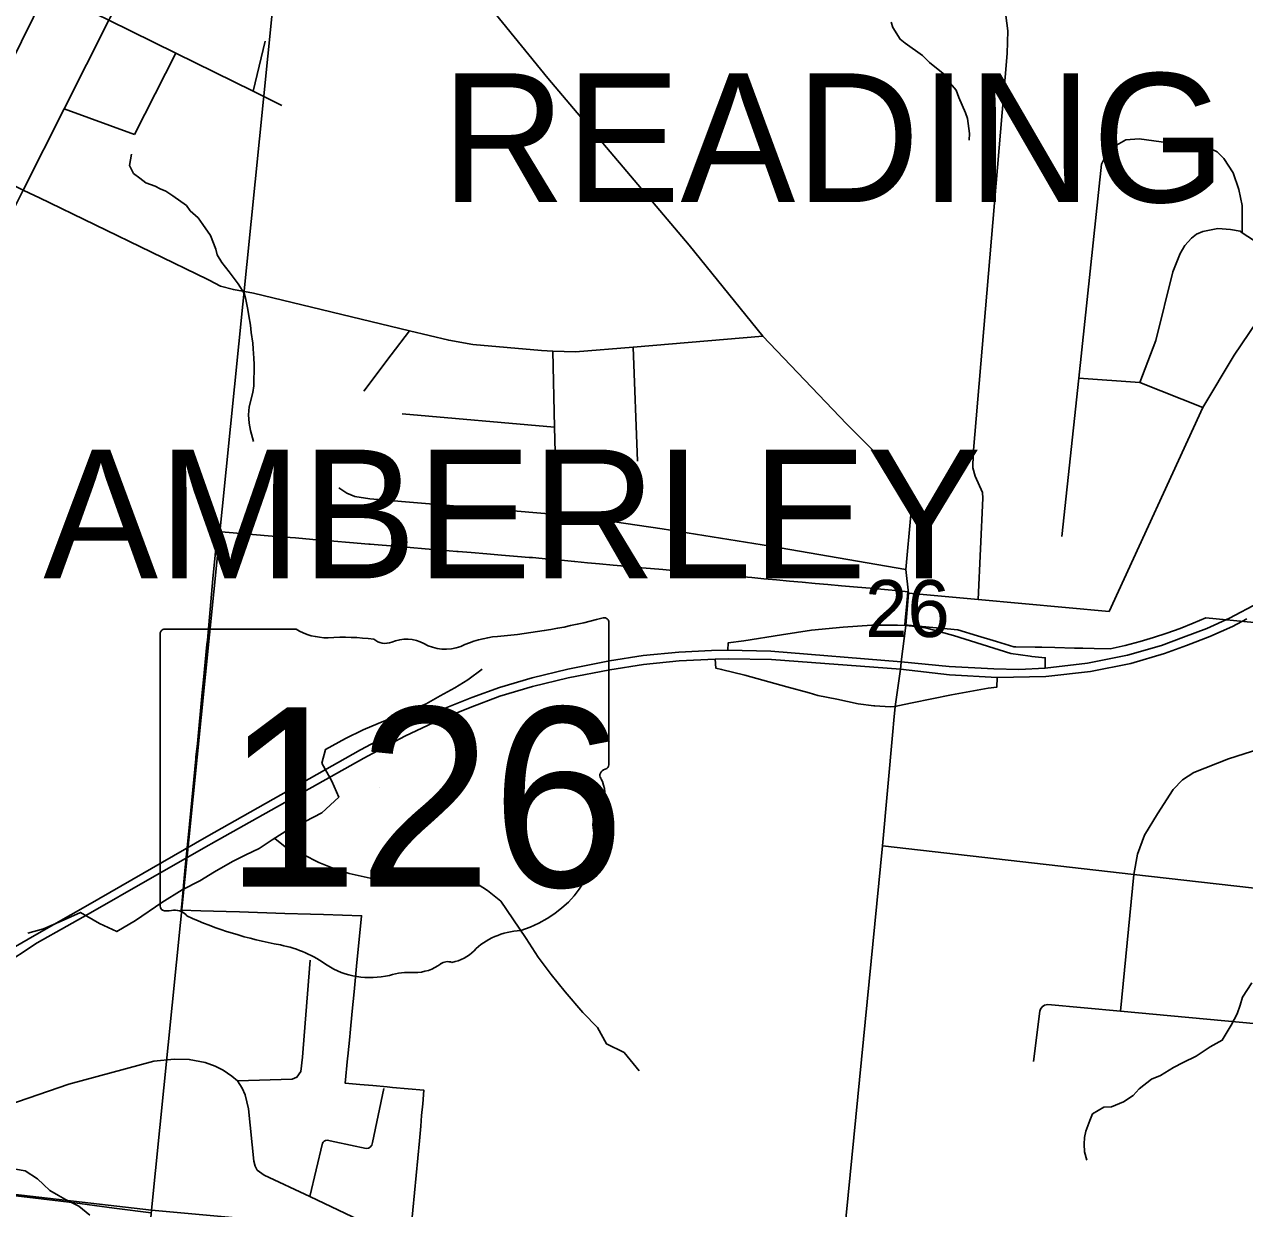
# Model space of a CAD drawing. Extents: x 0 to 34, y -3.9 to 26.2.
# Drawn here: x 3.881 to 4.778, y 18.269 to 19.139 of the extents above; entities that cross this region are included whole.
import ezdxf

# ---------------------------------------------------------------- set-up
doc = ezdxf.new("R2010")
doc.units = 0
for name, color, linetype in [('GM_X_City_Street', 7, 'Continuous'), ('GM_X_Corporation', 7, 'Continuous'), ('GM_X_Corporation_Text', 7, 'Continuous'), ('GM_X_County_Road', 7, 'Continuous'), ('GM_X_Interchange_Ramps', 7, 'Continuous'), ('GM_X_Minor_River', 7, 'Continuous'), ('GM_X_Section', 7, 'Continuous'), ('GM_X_Section_Text', 7, 'Continuous'), ('GM_X_State_Location', 7, 'Continuous'), ('GM_X_State_Route', 7, 'Continuous'), ('GM_X_State_Shield', 7, 'Continuous')]:
    doc.layers.add(name, color=color, linetype=linetype)

msp = doc.modelspace()

# ---------------------------------------------------------------- linework, layer by layer
at = {"layer": 'GM_X_City_Street'}
for p, q in [((4.04921, 19.08997), (4.05792, 19.12696)), ((3.9621, 19.05813), (3.99227, 19.11804)), ((3.91032, 19.07708), (3.9621, 19.05813)), ((4.3318, 18.81818), (4.32849, 18.90197)), ((4.27081, 18.84297), (4.15861, 18.85279))]:
    msp.add_line(p, q, dxfattribs=at)
for points in [[(4.67826, 18.70753), (4.74714, 18.8575), (4.77032, 18.89605), (4.81434, 18.96112), (4.90964, 19.07416), (4.93258, 19.10091), (4.93801, 19.1057), (4.94914, 19.11072), (5.07747, 19.16082), (5.09517, 19.17059), (5.09789, 19.1728), (5.1003, 19.17805), (5.11213, 19.29962), (5.11226, 19.30455), (5.1098, 19.31221), (5.09188, 19.36259)], [(4.5821, 18.7164), (4.58558, 18.79088), (4.58531, 18.79507), (4.57992, 18.80698), (4.57819, 18.81311), (4.57845, 18.82335), (4.60185, 19.10028), (4.60344, 19.1177), (4.60387, 19.13439), (4.60021, 19.16284), (4.59975, 19.1664), (4.5978, 19.17898), (4.59474, 19.19273), (4.58084, 19.22727), (4.57709, 19.24409), (4.5739, 19.26733), (4.57328, 19.28266), (4.57447, 19.28971), (4.58587, 19.35078)], [(3.42211, 19.34248), (3.42358, 19.34321), (3.42718, 19.34343), (3.49478, 19.33455), (3.5723, 19.32436), (3.65582, 19.28345), (3.73336, 19.24545), (3.80179, 19.21193), (3.89772, 19.16464), (3.94313, 19.14226), (3.99227, 19.11804), (4.04921, 19.08997), (4.07036, 19.07954)], [(3.83878, 18.93501), (3.88028, 19.01742), (3.91032, 19.07708), (3.94313, 19.14226), (3.94384, 19.14366), (3.96986, 19.19533), (4.00778, 19.27066)], [(3.83562, 19.03913), (3.89645, 19.16207), (3.89772, 19.16464)], [(4.64365, 18.76275), (4.65597, 18.87903), (4.67266, 19.03649), (4.67624, 19.04323), (4.6821, 19.04952), (4.69056, 19.05423), (4.70044, 19.05511), (4.7526, 19.04801), (4.75784, 19.0456), (4.76264, 19.04054), (4.76958, 19.0301), (4.77367, 19.01778), (4.77617, 19.006), (4.77613, 18.98603)], [(4.70078, 18.87589), (4.71256, 18.9067), (4.72524, 18.95724), (4.73051, 18.97077), (4.73404, 18.97653), (4.73876, 18.98194), (4.74249, 18.98486), (4.74724, 18.98703), (4.75829, 18.98902), (4.76758, 18.98834), (4.77455, 18.98706), (4.77613, 18.98603), (4.81434, 18.96112)], [(4.13059, 18.86949), (4.15063, 18.89615), (4.164, 18.91392)], [(4.27241, 18.7788), (4.27081, 18.84297), (4.26941, 18.89907)], [(4.65597, 18.87903), (4.70078, 18.87589), (4.74714, 18.8575)], [(4.11209, 18.7986), (4.11805, 18.79464), (4.12406, 18.79221), (4.13501, 18.79039), (4.27241, 18.7788), (4.28639, 18.77762), (4.34986, 18.76833), (4.42956, 18.75557), (4.52885, 18.73856)], [(4.53098, 18.72113), (4.5821, 18.7164), (4.67826, 18.70753)], [(4.68658, 18.41371), (4.69643, 18.51433), (4.69911, 18.52928), (4.70439, 18.54318), (4.7139, 18.55888), (4.72536, 18.57679), (4.73227, 18.58394), (4.74047, 18.5893), (4.76613, 18.59924), (4.78907, 18.6066), (4.7975, 18.60851), (4.79959, 18.60881), (4.80508, 18.60959), (4.89708, 18.60369), (4.98906, 18.5978), (5.03945, 18.59458), (5.04519, 18.59632), (5.05285, 18.59953), (5.12291, 18.64965)], [(4.51173, 18.53533), (4.69643, 18.51433), (4.943, 18.4863), (4.9457, 18.48511), (4.94732, 18.4837), (4.94851, 18.48197), (4.94965, 18.47928)], [(4.03765, 18.36248), (4.07793, 18.3638), (4.08138, 18.36528), (4.08417, 18.36939), (4.08549, 18.38007), (4.08598, 18.38621), (4.09106, 18.45138)], [(4.62277, 18.37679), (4.62751, 18.41388), (4.62794, 18.41536), (4.62911, 18.41687), (4.63091, 18.41815), (4.63332, 18.41865), (4.68658, 18.41371), (4.92726, 18.39138)], [(4.09075, 18.27748), (4.10013, 18.31674), (4.10069, 18.31748), (4.10148, 18.31828), (4.10244, 18.31876), (4.1036, 18.31892), (4.10925, 18.31763), (4.13227, 18.31284), (4.13403, 18.31317), (4.13533, 18.3139), (4.13635, 18.31516), (4.13693, 18.31727), (4.14515, 18.35692)]]:
    msp.add_lwpolyline(points, dxfattribs=at)
at = {"layer": 'GM_X_Corporation'}
for points in [[(4.16531, 18.25485), (4.17139, 18.31836), (4.17236, 18.3292), (4.17305, 18.33696), (4.17383, 18.34573), (4.17472, 18.35568), (4.15166, 18.35776), (4.14762, 18.35812), (4.13712, 18.35907), (4.12751, 18.35993), (4.11679, 18.3609), (4.11857, 18.37889), (4.11876, 18.38077), (4.12015, 18.39491), (4.12043, 18.39774), (4.12202, 18.41376), (4.12341, 18.42789), (4.12527, 18.44674), (4.12895, 18.48396), (4.1009, 18.48481), (4.09141, 18.4851), (4.07244, 18.48568), (4.0392, 18.48669), (4.02948, 18.48698), (4.02002, 18.48727), (4.0107, 18.48755), (3.99627, 18.48809), (3.9965, 18.49041), (3.99668, 18.49231), (3.99933, 18.51954), (4.00168, 18.54372), (4.00413, 18.56886), (4.0071, 18.59934), (4.0072, 18.60043), (4.0082, 18.61064), (4.01184, 18.64809), (4.01275, 18.65741), (4.01526, 18.68325), (4.01556, 18.68649), (4.01966, 18.7317), (4.02295, 18.76631), (4.06876, 18.76256), (4.08039, 18.76161), (4.09829, 18.76013), (4.10858, 18.75928), (4.11992, 18.75835), (4.1343, 18.75716), (4.13519, 18.75709), (4.144, 18.75635), (4.15346, 18.75556), (4.16464, 18.75463), (4.17558, 18.75371), (4.18759, 18.75271), (4.19892, 18.75176), (4.19997, 18.75168), (4.20947, 18.75089), (4.22088, 18.74995), (4.23186, 18.74905), (4.24356, 18.74809), (4.25204, 18.74739), (4.25444, 18.74717), (4.26624, 18.7461), (4.27569, 18.74525), (4.2855, 18.74436), (4.28572, 18.74434), (4.29489, 18.74347), (4.30377, 18.74262), (4.31369, 18.74167), (4.32238, 18.74084), (4.33137, 18.73998), (4.33486, 18.73965), (4.34121, 18.73911), (4.35027, 18.73834), (4.36016, 18.73751), (4.36875, 18.73678), (4.37364, 18.73637), (4.37819, 18.73595), (4.38772, 18.73507), (4.39667, 18.73425), (4.40615, 18.73338), (4.41562, 18.73251), (4.42452, 18.73169), (4.42777, 18.73139), (4.43382, 18.73085), (4.44343, 18.72998), (4.45281, 18.72913), (4.46233, 18.72827), (4.47156, 18.72744), (4.48169, 18.72652), (4.49329, 18.72548), (4.50275, 18.72462), (4.51313, 18.72368), (4.52422, 18.72268), (4.53037, 18.72212), (4.5294, 18.7107), (4.5285, 18.7011), (4.52819, 18.69783), (4.53319, 18.69735), (4.56725, 18.69408), (4.58158, 18.68976), (4.59565, 18.68553), (4.60835, 18.68171), (4.60977, 18.68168), (4.62389, 18.68139), (4.62884, 18.68129), (4.63832, 18.68107), (4.65297, 18.68073), (4.65898, 18.68059), (4.66739, 18.68039), (4.67906, 18.68012), (4.69012, 18.68264), (4.7011, 18.68552), (4.71097, 18.68844), (4.72075, 18.69164), (4.73044, 18.69514), (4.74002, 18.69891), (4.74949, 18.70296), (4.78505, 18.69949)], [(4.78505, 18.69949), (4.74949, 18.70296), (4.74002, 18.69891), (4.73044, 18.69514), (4.72075, 18.69164), (4.71097, 18.68844), (4.7011, 18.68552), (4.69012, 18.68264), (4.67906, 18.68012), (4.66739, 18.68039), (4.65898, 18.68059), (4.65297, 18.68073), (4.63832, 18.68107), (4.62884, 18.68129), (4.62389, 18.68139), (4.60977, 18.68168), (4.60835, 18.68171), (4.59565, 18.68553), (4.58158, 18.68976), (4.56725, 18.69408), (4.53319, 18.69735), (4.52819, 18.69783), (4.5285, 18.7011), (4.5294, 18.7107), (4.53037, 18.72212), (4.52422, 18.72268), (4.51313, 18.72368), (4.50275, 18.72462), (4.49329, 18.72548), (4.48169, 18.72652), (4.47156, 18.72744), (4.46233, 18.72827), (4.45281, 18.72913), (4.44343, 18.72998), (4.43382, 18.73085), (4.42777, 18.73139), (4.42452, 18.73169), (4.41562, 18.73251), (4.40615, 18.73338), (4.39667, 18.73425), (4.38772, 18.73507), (4.37819, 18.73595), (4.37364, 18.73637), (4.36875, 18.73678), (4.36016, 18.73751), (4.35027, 18.73834), (4.34121, 18.73911), (4.33486, 18.73965), (4.33137, 18.73998), (4.32238, 18.74084), (4.31369, 18.74167), (4.30377, 18.74262), (4.29489, 18.74347), (4.28572, 18.74434), (4.2855, 18.74436), (4.27569, 18.74525), (4.26624, 18.7461), (4.25444, 18.74717), (4.25204, 18.74739), (4.24356, 18.74809), (4.23186, 18.74905), (4.22088, 18.74995), (4.20947, 18.75089), (4.19997, 18.75168), (4.19892, 18.75176), (4.18759, 18.75271), (4.17558, 18.75371), (4.16464, 18.75463), (4.15346, 18.75556), (4.144, 18.75635), (4.13519, 18.75709), (4.1343, 18.75716), (4.11992, 18.75835), (4.10858, 18.75928), (4.09829, 18.76013), (4.08039, 18.76161), (4.06876, 18.76256), (4.02295, 18.76631), (4.01966, 18.7317), (4.01556, 18.68649), (4.01526, 18.68325), (4.01275, 18.65741), (4.01184, 18.64809), (4.0082, 18.61064), (4.0072, 18.60043), (4.0071, 18.59934), (4.00413, 18.56886), (4.00168, 18.54372), (3.99933, 18.51954), (3.99668, 18.49231), (3.9965, 18.49041), (3.99627, 18.48809), (4.0107, 18.48755), (4.02002, 18.48727), (4.02948, 18.48698), (4.0392, 18.48669), (4.07244, 18.48568), (4.09141, 18.4851), (4.1009, 18.48481), (4.12895, 18.48396), (4.12527, 18.44674), (4.12341, 18.42789), (4.12202, 18.41376), (4.12043, 18.39774), (4.12015, 18.39491), (4.11876, 18.38077), (4.11857, 18.37889), (4.11679, 18.3609), (4.12751, 18.35993), (4.13712, 18.35907), (4.14762, 18.35812), (4.15166, 18.35776), (4.17472, 18.35568), (4.17383, 18.34573), (4.17305, 18.33696), (4.17236, 18.3292), (4.17139, 18.31836), (4.16531, 18.25485)], [(3.81079, 18.24369), (3.81469, 18.28506), (3.82386, 18.28399), (3.85122, 18.28078), (3.8618, 18.27954), (3.88323, 18.27703), (3.91823, 18.27293), (3.94703, 18.26903), (3.97417, 18.26561)], [(3.97417, 18.26561), (3.94703, 18.26903), (3.91823, 18.27293), (3.88323, 18.27703), (3.8618, 18.27954), (3.85122, 18.28078), (3.82386, 18.28399), (3.81469, 18.28506), (3.81079, 18.24369)]]:
    msp.add_lwpolyline(points, dxfattribs=at)
at = {"layer": 'GM_X_County_Road'}
msp.add_line((4.52883, 18.6972), (4.53098, 18.72113), dxfattribs=at)
for points in [[(4.53098, 18.72113), (4.52885, 18.73856), (4.53258, 18.77854), (4.53234, 18.78419), (4.5313, 18.7911), (4.52889, 18.79799), (4.52511, 18.80491), (4.52344, 18.80707), (4.48528, 18.84561), (4.42374, 18.91006), (4.36973, 18.97676), (4.2658, 19.09969), (4.16901, 19.21867), (4.16657, 19.22277), (4.16239, 19.22983), (4.15559, 19.25162), (4.13078, 19.3038), (4.12786, 19.30994), (4.12527, 19.3129), (4.12087, 19.31675), (4.11023, 19.32165), (4.0164, 19.36489), (3.97125, 19.38569), (3.90768, 19.42367)], [(3.36715, 19.19868), (3.39229, 19.19223), (3.42359, 19.18468), (3.4673, 19.17661), (3.54493, 19.16227), (3.66913, 19.11339), (3.68493, 19.10718), (3.74097, 19.08512), (3.83562, 19.03913), (3.88028, 19.01742), (3.88909, 19.01315)], [(3.88909, 19.01315), (3.89173, 19.01186), (4.01588, 18.95152), (4.01682, 18.95104)], [(4.01682, 18.95104), (4.02524, 18.94672), (4.03465, 18.94419), (4.04938, 18.94152), (4.164, 18.91392), (4.19299, 18.90693), (4.21074, 18.9038), (4.26106, 18.89942), (4.26941, 18.89907), (4.28607, 18.89837), (4.32849, 18.90197), (4.42374, 18.91006)], [(4.52525, 18.66733), (4.5255, 18.67057), (4.52883, 18.6972)], [(4.51943, 18.6193), (4.5202, 18.6277), (4.52114, 18.63773), (4.52508, 18.66516), (4.52525, 18.66733)], [(4.22817, 17.22723), (4.24049, 17.50456), (4.243, 17.51666), (4.25054, 17.5336), (4.31287, 17.6317), (4.33274, 17.66299), (4.39508, 17.74681), (4.43243, 17.79354), (4.43716, 17.80294), (4.4401, 17.8177), (4.45785, 18.01565), (4.46135, 18.0547), (4.48088, 18.22126), (4.51173, 18.53533), (4.51943, 18.6193)], [(3.76523, 18.29845), (3.77257, 18.30043), (3.85927, 18.3416), (3.88385, 18.34978), (3.91385, 18.36018), (3.97632, 18.37695), (3.99112, 18.37843), (4.0023, 18.37826), (4.01397, 18.37613), (4.02121, 18.37333), (4.02729, 18.37037), (4.03353, 18.36594), (4.03765, 18.36248), (4.0411, 18.35706), (4.0434, 18.35229), (4.04583, 18.34194), (4.04965, 18.3035), (4.05067, 18.29972), (4.05218, 18.29699), (4.05721, 18.29327), (4.09075, 18.27748), (4.1427, 18.25266)]]:
    msp.add_lwpolyline(points, dxfattribs=at)
at = {"layer": 'GM_X_Interchange_Ramps'}
for points in [[(4.52883, 18.6972), (4.52277, 18.6975), (4.50387, 18.69756), (4.48292, 18.69603), (4.45958, 18.69396), (4.43741, 18.69049), (4.40988, 18.68595), (4.39833, 18.68452), (4.39817, 18.67907)], [(4.6214, 18.67457), (4.62029, 18.67467), (4.60605, 18.6768), (4.56405, 18.68996), (4.54428, 18.69531), (4.53877, 18.69621), (4.53129, 18.69697), (4.52883, 18.6972)], [(4.38889, 18.67247), (4.38932, 18.66583), (4.39344, 18.66498), (4.41053, 18.66086), (4.44152, 18.65231), (4.45777, 18.64773)], [(4.63139, 18.66603), (4.63139, 18.67358), (4.6214, 18.67457)], [(4.52114, 18.63773), (4.52314, 18.63828), (4.53363, 18.64046), (4.56256, 18.64635), (4.58931, 18.65111), (4.59581, 18.65199), (4.59592, 18.65905)], [(4.45777, 18.64773), (4.46427, 18.64589), (4.47822, 18.64303), (4.49394, 18.63973), (4.50536, 18.6383), (4.50621, 18.63823), (4.51745, 18.63754), (4.52114, 18.63773)]]:
    msp.add_lwpolyline(points, dxfattribs=at)
at = {"layer": 'GM_X_Minor_River'}
for points in [[(4.5181, 19.14074), (4.51947, 19.13689), (4.52483, 19.1283), (4.52852, 19.12549), (4.54108, 19.11622), (4.54619, 19.11107), (4.55872, 19.10104), (4.56156, 19.09599), (4.56591, 19.09086), (4.56798, 19.08545), (4.57286, 19.07423), (4.57421, 19.06999), (4.57568, 19.05891), (4.57548, 19.05397)], [(4.04955, 18.8325), (4.04721, 18.84058), (4.04628, 18.84594), (4.04576, 18.85204), (4.04638, 18.8581), (4.04908, 18.86863), (4.04965, 18.87355), (4.04988, 18.88913), (4.04968, 18.8937), (4.04919, 18.90056), (4.04898, 18.90475), (4.04778, 18.91278), (4.04723, 18.91812), (4.04598, 18.92502), (4.0454, 18.9296), (4.04379, 18.93689), (4.04281, 18.94112), (4.03817, 18.94853), (4.03166, 18.95716), (4.02624, 18.96423), (4.02266, 18.9697), (4.02168, 18.97392), (4.0179, 18.98396), (4.01215, 18.99218), (4.00891, 18.99688), (4.00303, 19.00206), (4.00015, 19.00598), (3.99017, 19.01324), (3.98498, 19.0165), (3.98087, 19.01818), (3.97715, 19.02024), (3.97041, 19.0228), (3.96598, 19.02603), (3.96118, 19.02964), (3.95837, 19.03546), (3.95984, 19.04377)], [(4.21741, 18.66521), (4.20702, 18.65742), (4.19743, 18.65152), (4.18669, 18.64564), (4.17634, 18.63975), (4.16486, 18.63503), (4.15072, 18.62921), (4.14116, 18.62521), (4.13006, 18.62048), (4.11705, 18.61426), (4.10248, 18.60618), (4.09963, 18.59597), (4.10697, 18.5829), (4.11206, 18.57102), (4.09971, 18.55947), (4.08745, 18.55324), (4.07596, 18.54775), (4.06329, 18.53963), (4.05368, 18.53335), (4.04373, 18.5286), (4.03415, 18.52384), (4.02073, 18.51611), (4.00998, 18.50947), (3.99696, 18.50287), (3.98199, 18.49365), (3.96276, 18.48033), (3.94895, 18.47223), (3.93616, 18.47817), (3.92228, 18.48642), (3.90812, 18.47984), (3.89511, 18.47439), (3.88367, 18.47118)], [(4.06505, 18.54076), (4.07268, 18.53451), (4.08585, 18.52894), (4.0975, 18.52302), (4.10843, 18.51863), (4.11974, 18.51499), (4.13523, 18.51166), (4.14927, 18.51177), (4.16068, 18.51307), (4.17362, 18.51511), (4.18612, 18.51411), (4.199, 18.51273), (4.21182, 18.50868), (4.22157, 18.50242), (4.23129, 18.49463), (4.24015, 18.48153), (4.24975, 18.46729), (4.25859, 18.45343), (4.26822, 18.44071), (4.27861, 18.42796), (4.2916, 18.41289), (4.3024, 18.40166), (4.309, 18.38975), (4.32178, 18.38342), (4.33291, 18.36991)], [(4.66184, 18.30421), (4.66018, 18.31036), (4.66002, 18.31607), (4.66022, 18.321), (4.66115, 18.32552), (4.66412, 18.33338), (4.66622, 18.33823), (4.67439, 18.34322), (4.6801, 18.34336), (4.68899, 18.34717), (4.69601, 18.35182), (4.70038, 18.35658), (4.7094, 18.36381), (4.71597, 18.36657), (4.7257, 18.37225), (4.73269, 18.37614), (4.74237, 18.38068), (4.75252, 18.38748), (4.76145, 18.39243), (4.76797, 18.40357), (4.77247, 18.41174), (4.77463, 18.41812), (4.77638, 18.42412), (4.78325, 18.43448)], [(3.8325, 18.28122), (3.83749, 18.28253), (3.84294, 18.28573), (3.84843, 18.29006), (3.85506, 18.29435), (3.86049, 18.29716), (3.86887, 18.29757), (3.87458, 18.29772), (3.88174, 18.29628), (3.89063, 18.29059), (3.89502, 18.28623), (3.89979, 18.28185), (3.90611, 18.27817), (3.91131, 18.27529), (3.921, 18.27033), (3.92911, 18.26391)]]:
    msp.add_lwpolyline(points, dxfattribs=at)
at = {"layer": 'GM_X_Section'}
for points in [[(3.06078, 19.39362), (4.07507, 19.26688), (3.97441, 18.26756), (2.95688, 18.38489)], [(4.07507, 19.26688), (5.08525, 19.17848), (4.98981, 18.17527), (3.97441, 18.26756)], [(2.95688, 18.38489), (3.97441, 18.26756), (3.88035, 17.25787), (2.86031, 17.36388)]]:
    msp.add_lwpolyline(points, close=True, dxfattribs=at)
at = {"layer": 'GM_X_State_Route'}
msp.add_line((3.97315, 18.511), (4.0167, 18.53588), dxfattribs=at)
for points in [[(4.63139, 18.66603), (4.66233, 18.66953), (4.69194, 18.67546), (4.71672, 18.68269), (4.73295, 18.68861), (4.75006, 18.69519), (4.76673, 18.70265), (4.788, 18.71406)], [(4.0167, 18.53588), (4.01844, 18.53688), (4.13052, 18.59983), (4.16057, 18.61584), (4.18623, 18.6279), (4.20882, 18.63689), (4.23053, 18.64523), (4.25444, 18.65246), (4.28076, 18.65882), (4.31125, 18.66475), (4.33603, 18.66869), (4.36235, 18.67133), (4.38889, 18.67247), (4.39854, 18.67286), (4.43012, 18.6722), (4.52508, 18.66516), (4.56106, 18.66102), (4.59592, 18.65905), (4.63169, 18.6597), (4.66458, 18.66343), (4.69419, 18.66935), (4.71898, 18.67659), (4.73521, 18.68251), (4.75232, 18.68909), (4.76898, 18.69655), (4.77962, 18.70225)], [(3.87275, 18.46022), (3.89033, 18.47045), (3.92765, 18.49157), (4.01504, 18.54187), (4.12803, 18.60584), (4.15572, 18.62064), (4.18304, 18.63354), (4.20998, 18.64439), (4.23032, 18.65168), (4.25423, 18.65892), (4.28055, 18.66528), (4.31104, 18.6712), (4.33582, 18.67515), (4.36214, 18.67778), (4.38618, 18.67881), (4.39817, 18.67907), (4.42975, 18.67842), (4.5255, 18.67057), (4.56069, 18.66723), (4.59358, 18.66537), (4.61193, 18.66496), (4.63139, 18.66603)], [(3.91224, 18.47628), (3.92786, 18.48512), (3.97315, 18.511)], [(3.36566, 18.28122), (3.42099, 18.275), (3.45542, 18.27324), (3.48898, 18.27412), (3.51442, 18.27632), (3.54338, 18.28092), (3.57101, 18.28728), (3.59294, 18.2932), (3.63117, 18.30581), (3.65523, 18.31316), (3.67739, 18.32084), (3.70063, 18.33005), (3.72827, 18.34365), (3.73752, 18.34979), (3.74671, 18.35585), (3.75547, 18.36163), (3.79799, 18.39515), (3.82302, 18.41603), (3.84693, 18.43467), (3.86382, 18.4463), (3.89054, 18.464), (3.91224, 18.47628)]]:
    msp.add_lwpolyline(points, dxfattribs=at)
at = {"layer": 'GM_X_State_Shield'}
for p, q in [((4.31054, 18.59491), (4.31054, 18.6996)), ((3.98096, 18.6912), (3.98096, 18.49108)), ((4.08072, 18.69464), (3.9842, 18.69464)), ((4.31051, 18.59494), (4.31054, 18.59491))]:
    msp.add_line(p, q, dxfattribs=at)
for centre, major_axis, start_param, end_param in [((4.19314, 18.96747), (0.34952, 0), 4.814394, 5.042369), ((4.30689, 18.70003), (0.00367, 0), 6.141152, 7.989035), ((3.98473, 18.69162), (0.00382, 0), 1.712693, 3.28349), ((4.10371, 18.71787), (0.03703, 0), 4.042523, 4.731795), ((4.11599, 18.58229), (0.13295, 0), 1.404758, 1.657858), ((4.14617, 18.69266), (0.01068, 0), 3.836095, 5.185415), ((4.16186, 18.66953), (0.02221, 0), 0.950623, 2.079405), ((4.19053, 18.70125), (0.02672, 0), 4.081561, 5.145723), ((4.23772, 18.63352), (0.07032, 0), 1.699011, 2.107814), ((4.30969, 18.58723), (0.00568, 0), 1.883978, 3.671073), ((4.30663, 18.59451), (0.00393, 0), 5.05454, 6.418171), ((4.27357, 18.57399), (0.03409, 0), 5.934695, 6.695948), ((4.32369, 18.5511), (0.0248, 0), 2.387724, 3.262537), ((4.21272, 18.53779), (0.08742, 0), 5.101752, 6.440018), ((3.98477, 18.49064), (0.00385, 0), 3.00124, 4.508301), ((3.98535, 18.51111), (0.0294, 0), 4.665946, 4.897461), ((3.99137, 18.47953), (0.0106, 0), 0.519207, 1.627899), ((4.12519, 18.65933), (0.2524, 0), 4.195997, 4.488961), ((4.24958, 18.43489), (0.04788, 0), 1.647645, 2.488434), ((4.04994, 18.40117), (0.07897, 0), 0.823519, 1.323587), ((4.18892, 18.47168), (0.02824, 0), 4.937069, 5.64225), ((4.13536, 18.47854), (0.05011, 0), 4.026481, 4.996735), ((4.16797, 18.46355), (0.0267, 0), 4.691044, 5.507374), ((4.19212, 18.44417), (0.00752, 0), 1.147584, 2.315152), ((4.16431, 18.40935), (0.04118, 0), 1.495662, 1.94098)]:
    msp.add_ellipse(centre, major_axis=major_axis, ratio=0.8, start_param=start_param, end_param=end_param, dxfattribs=at)

# ---------------------------------------------------------------- texts
at = {"layer": 'GM_X_Corporation_Text'}
for s, p in [('READING', (4.18735, 19.00849)), ('AMBERLEY', (3.89494, 18.73185))]:
    msp.add_text(s, height=0.094697, rotation=0.00001, dxfattribs=at).set_placement(p)
at = {"layer": 'GM_X_Section_Text'}
msp.add_text('26', height=0.041856, rotation=0.00001, dxfattribs=at).set_placement((4.49894, 18.68883))
at = {"layer": 'GM_X_State_Location'}
for s, p in [('s', (4.14205, 18.57783)), ('r', (4.14204, 18.57783))]:
    msp.add_text(s, height=0.000189, dxfattribs=at).set_placement(p)
msp.add_text('126', height=0.000189, rotation=0.00001, dxfattribs=at).set_placement((4.07519, 18.56405))
at = {"layer": 'GM_X_State_Shield'}
msp.add_text('126', height=0.131836, dxfattribs=at).set_placement((4.02838, 18.50519))

doc.saveas('drawing.dxf')
